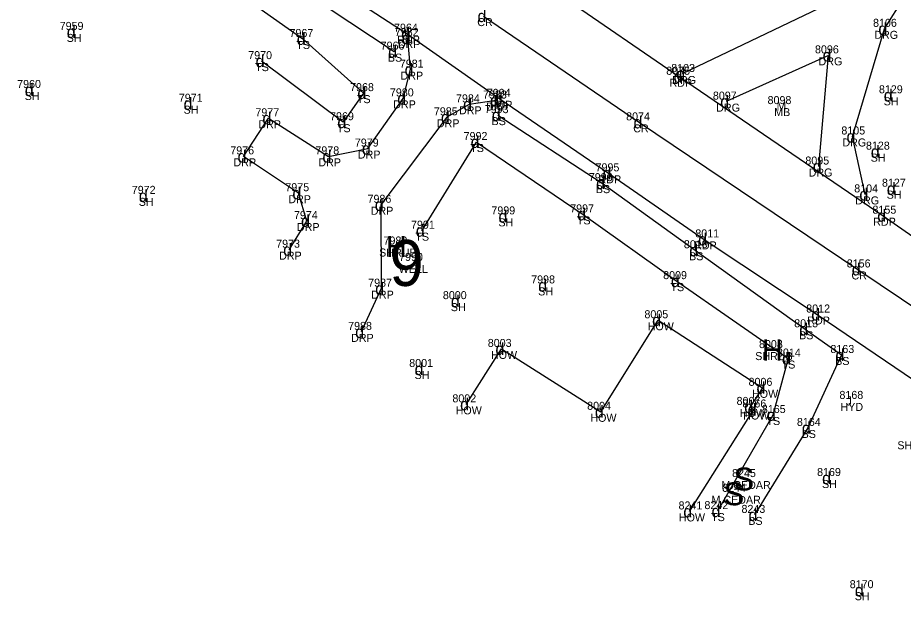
# Model space of a CAD drawing. Extents: x 69415 to 80913, y 7576 to 15059.
# Drawn here: x 76868.4 to 77089.7, y 13501.5 to 13647.1 of the extents above; entities that cross this region are included whole.
import ezdxf

# ---------------------------------------------------------------- set-up
doc = ezdxf.new("R2010")
doc.units = 0
for name, color, linetype in [('Level 11', 7, 'Continuous'), ('Level 12', 7, 'Continuous'), ('Level 13', 7, 'Continuous'), ('Level 14', 7, 'Continuous'), ('Level 15', 7, 'Continuous'), ('Level 46', 7, 'Continuous'), ('Level 47', 7, 'Continuous'), ('Level 48', 7, 'Continuous')]:
    doc.layers.add(name, color=color, linetype=linetype)

msp = doc.modelspace()

# ---------------------------------------------------------------- linework, layer by layer
at = {"layer": 'Level 11'}
for p, q in [((77084.95, 13644.35), (77105.53, 13676.86)), ((76993.01, 13660.33), (77033.78, 13632.37)), ((76949.23, 13653.81), (76965.72, 13643.14)), ((77074.41, 13652.27), (77034.45, 13633.07)), ((76965.72, 13643.14), (76988.86, 13626.86)), ((77076.99, 13617.45), (77084.95, 13644.35)), ((76966.55, 13634.15), (76965.87, 13642.02)), ((77071.02, 13637.72), (77045.44, 13626.16)), ((77068.55, 13609.94), (77071.02, 13637.72)), ((76964.72, 13626.97), (76966.55, 13634.15)), ((77033.78, 13632.37), (77084.68, 13597.65)), ((76955.89, 13614.43), (76964.72, 13626.97)), ((76981.16, 13625.48), (76975.63, 13622.24)), ((76987.9, 13626.43), (76981.16, 13625.48)), ((76988.86, 13626.86), (77016.04, 13608.24)), ((76924.8, 13612.48), (76931.02, 13622)), ((76931.02, 13622), (76946.02, 13612.48)), ((76975.63, 13622.24), (76959.1, 13600.38)), ((77080.2, 13602.97), (77076.99, 13617.45)), ((76946.02, 13612.48), (76955.89, 13614.43)), ((76938.51, 13603.27), (76924.8, 13612.48)), ((77016.04, 13608.24), (77039.91, 13591.73)), ((76940.66, 13596.32), (76938.51, 13603.27)), ((76959.1, 13600.38), (76959.21, 13579.42)), ((76936.21, 13589.16), (76940.66, 13596.32)), ((77084.68, 13597.65), (77123.55, 13570.31)), ((77039.91, 13591.73), (77068.2, 13572.96)), ((76959.21, 13579.42), (76954.2, 13568.61)), ((77068.2, 13572.96), (77107.62, 13546.12))]:
    msp.add_line(p, q, dxfattribs=at)
at = {"layer": 'Level 13'}
for p, q in [((77014.1, 13548.65), (77028.41, 13571.53)), ((77028.41, 13571.53), (77054.49, 13554.64)), ((76980.42, 13550.51), (76989.25, 13564.36)), ((76989.25, 13564.36), (77014.1, 13548.65)), ((77054.49, 13554.64), (77051.43, 13549.87)), ((77051.43, 13549.87), (77052.29, 13549.22)), ((77052.29, 13549.22), (77036.21, 13523.75))]:
    msp.add_line(p, q, dxfattribs=at)
at = {"layer": 'Level 48'}
for p, q in [((76899.21, 13670.6), (76939.59, 13641.81)), ((76945.72, 13649.73), (76962.44, 13638.65)), ((76984.77, 13647.53), (77023.76, 13620.97)), ((76939.59, 13641.81), (76954.74, 13628.28)), ((76949.74, 13621.01), (76929.31, 13636.28)), ((76954.74, 13628.28), (76949.74, 13621.01)), ((76988.34, 13622.78), (77014.41, 13605.79)), ((77023.76, 13620.97), (77078.3, 13584.22)), ((76969.34, 13593.9), (76983.06, 13616.06)), ((76983.06, 13616.06), (77009.7, 13597.98)), ((77014.41, 13605.79), (77037.71, 13589.02)), ((77009.7, 13597.98), (77033.09, 13581.3)), ((77037.71, 13589.02), (77065.2, 13569.27)), ((77078.3, 13584.22), (77116.24, 13558.76)), ((77033.09, 13581.3), (77060.88, 13561.96)), ((77065.2, 13569.27), (77074.22, 13562.85)), ((77074.22, 13562.85), (77065.84, 13544.61)), ((77060.88, 13561.96), (77057.08, 13547.84)), ((77057.08, 13547.84), (77043.25, 13523.83)), ((77065.84, 13544.61), (77052.51, 13522.88))]:
    msp.add_line(p, q, dxfattribs=at)

# ---------------------------------------------------------------- texts
at = {"layer": 'Level 12'}
msp.add_text('M', height=2.2, dxfattribs=at).set_placement((77058.01, 13623.94))
at = {"layer": 'Level 14'}
for s, height, p in [('H', 5.3, (76960.41, 13587.3)), ('H', 5.3, (77054.4, 13561.42)), ('S', 5.75, (77047.29, 13528.97)), ('S', 5.75, (77044.82, 13525.28))]:
    msp.add_text(s, height=height, dxfattribs=at).set_placement(p)
at = {"layer": 'Level 15'}
for s, height, p in [('9', 11.5, (76961.28, 13580.1)), ('J', 2.26, (77075.34, 13550.24))]:
    msp.add_text(s, height=height, dxfattribs=at).set_placement(p)
at = {"layer": 'Level 46'}
for s, p in [('CR', (76983.21, 13645.03)), ('8106', (77082.13, 13644.85)), ('7959', (76878.85, 13644.08)), ('7964', (76962.41, 13643.64)), ('SH', (76880.6, 13641.08)), ('7967', (76936.29, 13642.31)), ('7982', (76962.61, 13642.52)), ('RDP', (76963.21, 13640.64)), ('DRG', (77082.44, 13641.85)), ('TS', (76938, 13639.31)), ('7966', (76959.07, 13639.15)), ('DRP', (76963.36, 13639.52)), ('8096', (77067.62, 13638.22)), ('7970', (76925.97, 13636.78)), ('BS', (76960.88, 13636.15)), ('TS', (76927.72, 13633.78)), ('7981', (76963.85, 13634.65)), ('DRG', (77068.51, 13635.22)), ('DRP', (76964.04, 13631.65)), ('8075', (77030.44, 13632.87)), ('8103', (77031.68, 13633.57)), ('7960', (76868.22, 13629.57)), ('RDP', (77031.26, 13629.87)), ('DRG', (77031.94, 13630.57)), ('7968', (76951.43, 13628.78)), ('7980', (76961.38, 13627.47)), ('7994', (76985.6, 13627.36)), ('8129', (77083.6, 13628.24)), ('SH', (76870.11, 13626.57)), ('7971', (76908.63, 13626.13)), ('TS', (76953.15, 13625.78)), ('7984', (76977.9, 13625.98)), ('7983', (76984.64, 13626.93)), ('8097', (77042.1, 13626.66)), ('8098', (77055.77, 13625.54)), ('SH', (77084.79, 13625.24)), ('SH', (76909.81, 13623.13)), ('DRP', (76962.21, 13624.47)), ('7985', (76972.37, 13622.74)), ('DRP', (76978.65, 13622.98)), ('7993', (76985.08, 13623.28)), ('DRP', (76985.39, 13623.93)), ('RDP', (76986.35, 13624.36)), ('DRG', (77042.93, 13623.66)), ('7977', (76927.76, 13622.5)), ('7969', (76946.42, 13621.51)), ('8074', (77020.42, 13621.47)), ('MB', (77057.42, 13622.54)), ('DRP', (76928.5, 13619.5)), ('TS', (76948.15, 13618.51)), ('DRP', (76973.12, 13619.74)), ('BS', (76986.79, 13620.28)), ('CR', (77022.19, 13618.47)), ('7992', (76979.8, 13616.56)), ('8105', (77074.21, 13617.95)), ('7979', (76952.62, 13614.93)), ('DRG', (77074.47, 13614.95)), ('8128', (77080.36, 13614.16)), ('7976', (76921.49, 13612.98)), ('7978', (76942.76, 13612.98)), ('DRP', (76953.38, 13611.93)), ('TS', (76981.47, 13613.56)), ('DRP', (76922.29, 13609.98)), ('DRP', (76943.51, 13609.98)), ('8095', (77065.21, 13610.44)), ('SH', (77081.54, 13611.16)), ('7995', (77012.78, 13608.74)), ('DRG', (77066.04, 13607.44)), ('7996', (77011.09, 13606.29)), ('RDP', (77013.52, 13605.74)), ('7972', (76896.87, 13603.11)), ('7975', (76935.25, 13603.77)), ('BS', (77012.85, 13603.29)), ('8104', (77077.43, 13603.47)), ('8127', (77084.36, 13604.9)), ('DRP', (76936, 13600.77)), ('7986', (76955.79, 13600.88)), ('SH', (77085.54, 13601.9)), ('SH', (76898.62, 13600.11)), ('7997', (77006.44, 13598.48)), ('DRG', (77077.69, 13600.47)), ('7974', (76937.4, 13596.82)), ('DRP', (76956.59, 13597.88)), ('7999', (76986.74, 13597.98)), ('8155', (77081.99, 13598.15)), ('7991', (76966.65, 13594.4)), ('SH', (76988.5, 13594.98)), ('TS', (77008.11, 13595.48)), ('RDP', (77082.17, 13595.15)), ('DRP', (76938.15, 13593.82)), ('8011', (77037.71, 13592.23)), ('7973', (76932.95, 13589.66)), ('7989', (76959.79, 13590.45)), ('TS', (76967.75, 13591.4)), ('8010', (77034.85, 13589.52)), ('SHRUB', (76958.69, 13587.45)), ('RDP', (77037.4, 13589.23)), ('DRP', (76933.7, 13586.66)), ('7990', (76963.68, 13586.35)), ('BS', (77036.15, 13586.52)), ('WELL', (76963.59, 13583.35)), ('8156', (77075.56, 13584.72)), ('7998', (76996.69, 13580.73)), ('8009', (77029.67, 13581.8)), ('CR', (77076.74, 13581.72)), ('7987', (76955.95, 13579.92)), ('TS', (77031.5, 13578.8)), ('DRP', (76956.7, 13576.92)), ('8000', (76974.62, 13576.8)), ('SH', (76998.44, 13577.73)), ('SH', (76976.61, 13573.8)), ('8005', (77024.99, 13572.03)), ('8012', (77065.43, 13573.46)), ('8013', (77062.43, 13569.77)), ('RDP', (77065.69, 13570.46)), ('7988', (76950.94, 13569.11)), ('HOW', (77025.8, 13569.03)), ('DRP', (76951.69, 13566.11)), ('BS', (77063.64, 13566.77)), ('8003', (76985.84, 13564.86)), ('8008', (77053.63, 13564.57)), ('8163', (77071.48, 13563.35)), ('HOW', (76986.64, 13561.86)), ('SHRUB', (77052.68, 13561.57)), ('8014', (77058.11, 13562.46)), ('8001', (76966.21, 13559.85)), ('TS', (77059.29, 13559.46)), ('BS', (77072.67, 13560.35)), ('SH', (76967.55, 13556.85)), ('8006', (77051.02, 13555.14)), ('HOW', (77051.88, 13552.14)), ('8002', (76977, 13551.01)), ('8007', (77048.02, 13550.37)), ('8166', (77049.49, 13549.72)), ('8168', (77073.73, 13551.87)), ('HOW', (76977.81, 13548.01)), ('8004', (77010.68, 13549.15)), ('8165', (77054.34, 13548.34)), ('HYD', (77073.99, 13548.87)), ('HOW', (77011.48, 13546.15)), ('HOW', (77048.82, 13547.37)), ('HOW', (77049.67, 13546.72)), ('TS', (77055.49, 13545.34)), ('8164', (77063.1, 13545.11)), ('BS', (77064.28, 13542.11)), ('SHRUB', (77088.2, 13539.28)), ('8245', (77046.9, 13532.34)), ('8169', (77068.14, 13532.6)), ('M.CEDAR', (77044.22, 13529.34)), ('8244', (77044.43, 13528.65)), ('SH', (77069.38, 13529.6)), ('M.CEDAR', (77041.75, 13525.65)), ('8241', (77033.52, 13524.25)), ('8242', (77039.99, 13524.33)), ('8243', (77049.25, 13523.38)), ('HOW', (77033.6, 13521.25)), ('TS', (77041.66, 13521.33)), ('BS', (77050.95, 13520.38)), ('8170', (77076.3, 13504.57)), ('SH', (77077.56, 13501.57))]:
    msp.add_text(s, height=2, dxfattribs=at).set_placement(p)
at = {"layer": 'Level 47'}
for p in [(76983.27, 13646.03), (76880.62, 13642.08), (76964.22, 13641.64), (77083.45, 13642.85), (76938.09, 13640.31), (76964.37, 13640.52), (76960.94, 13637.15), (77069.52, 13636.22), (76927.81, 13634.78), (76965.05, 13632.65), (77032.28, 13630.87), (77032.95, 13631.57), (76870.12, 13627.57), (76953.24, 13626.78), (77084.8, 13626.24), (76909.82, 13624.13), (76963.22, 13625.47), (76979.66, 13623.98), (76986.4, 13624.93), (76987.36, 13625.36), (77043.94, 13624.66), (76929.52, 13620.5), (76948.24, 13619.51), (76974.13, 13620.74), (76986.84, 13621.28), (77022.26, 13619.47), (77075.49, 13615.95), (76954.39, 13612.93), (76981.56, 13614.56), (76923.3, 13610.98), (76944.52, 13610.98), (77081.56, 13612.16), (77067.05, 13608.44), (77014.54, 13606.74), (77012.91, 13604.29), (76937.01, 13601.77), (77085.56, 13602.9), (76898.63, 13601.11), (77078.7, 13601.47), (76957.6, 13598.88), (76988.51, 13595.98), (77008.2, 13596.48), (77083.18, 13596.15), (76939.16, 13594.82), (76967.84, 13592.4), (77038.41, 13590.23), (76934.71, 13587.66), (77036.21, 13587.52), (77076.8, 13582.72), (77031.59, 13579.8), (76957.71, 13577.92), (76998.45, 13578.73), (76976.62, 13574.8), (77066.7, 13571.46), (77026.91, 13570.03), (76952.7, 13567.11), (77063.7, 13567.77), (76987.75, 13562.86), (77059.38, 13560.46), (77072.72, 13561.35), (76967.56, 13557.85), (77052.99, 13553.14), (76978.92, 13549.01), (77012.6, 13547.15), (77049.93, 13548.37), (77050.79, 13547.72), (77055.58, 13546.34), (77064.34, 13543.11), (77069.39, 13530.6), (77034.71, 13522.25), (77041.75, 13522.33), (77051.01, 13521.38), (77077.58, 13502.57)]:
    msp.add_text('d', height=3, dxfattribs=at).set_placement(p)

doc.saveas('drawing.dxf')
